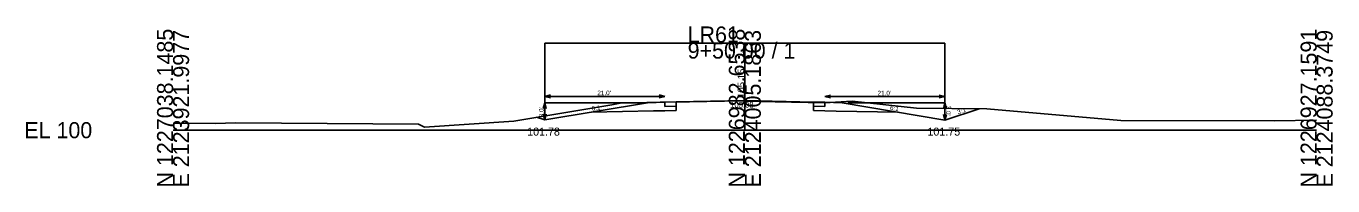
# Model space of a CAD drawing. Extents: x 2126751 to 2128979, y 1225108 to 1234639.
# Drawn here: x 2126750.9 to 2126979.4, y 1234607.5 to 1234635.3 of the extents above; entities that cross this region are included whole.
import ezdxf

# ---------------------------------------------------------------- set-up
doc = ezdxf.new("R2010")
doc.units = 0
for name, color, linetype in [('XS_CELL', 7, 'Continuous'), ('XS_M_DITCH', 7, 'Continuous'), ('XS_P_FINISHED_GRADE', 7, 'Continuous'), ('XS_P_FINISHED_GRADE_ELEV_TX', 7, 'Continuous'), ('XS_P_SUBGRADE_GRANULAR', 7, 'Continuous'), ('XS_P_SUBGRADE_LEVELING', 7, 'Continuous'), ('XS_P_SUBGRADE_PAVEMENT', 7, 'Continuous'), ('XS_P_TX_CLEARZONE', 7, 'Continuous'), ('XS_P_TX_DCH', 7, 'Continuous'), ('XS_P_TX_FS_BS', 7, 'Continuous'), ('XS_X_GROUND', 7, 'Continuous'), ('XS_X_GROUND_TX', 7, 'Continuous')]:
    doc.layers.add(name, color=color, linetype=linetype)

msp = doc.modelspace()

# ---------------------------------------------------------------- linework, layer by layer
at = {"layer": 'XS_CELL'}
for p, q in [((2126876.61, 1234617.21), (2126876.61, 1234632.49)), ((2126776.61, 1234617.21), (2126876.61, 1234617.21)), ((2126876.61, 1234617.21), (2126976.61, 1234617.21))]:
    msp.add_line(p, q, dxfattribs=at)
at = {"layer": 'XS_M_DITCH'}
for p, q in [((2126841.61, 1234618.99), (2126841.61, 1234632.39)), ((2126841.61, 1234632.39), (2126911.61, 1234632.39)), ((2126911.61, 1234632.39), (2126911.61, 1234618.96))]:
    msp.add_line(p, q, dxfattribs=at)
at = {"layer": 'XS_P_FINISHED_GRADE'}
for p, q in [((2126864.61, 1234622.15), (2126876.61, 1234622.36)), ((2126876.61, 1234622.36), (2126888.61, 1234622.12)), ((2126859.61, 1234621.99), (2126841.61, 1234618.99)), ((2126862.61, 1234622.11), (2126859.61, 1234621.99)), ((2126864.61, 1234622.15), (2126862.61, 1234622.11)), ((2126888.61, 1234622.12), (2126890.61, 1234622.08)), ((2126890.61, 1234622.08), (2126893.61, 1234621.96)), ((2126893.61, 1234621.96), (2126911.61, 1234618.96)), ((2126911.61, 1234618.96), (2126917.61, 1234620.96)), ((2126841.61, 1234618.99), (2126840.19, 1234619.46))]:
    msp.add_line(p, q, dxfattribs=at)
at = {"layer": 'XS_P_SUBGRADE_GRANULAR'}
for p, q in [((2126860.61, 1234620.57), (2126849.79, 1234620.35)), ((2126862.61, 1234620.61), (2126860.61, 1234620.57)), ((2126864.61, 1234620.65), (2126862.61, 1234620.61)), ((2126864.61, 1234620.65), (2126864.61, 1234621.4)), ((2126888.61, 1234620.62), (2126888.61, 1234621.37)), ((2126888.61, 1234620.62), (2126890.61, 1234620.58)), ((2126890.61, 1234620.58), (2126892.61, 1234620.54)), ((2126892.61, 1234620.54), (2126903.43, 1234620.33))]:
    msp.add_line(p, q, dxfattribs=at)
at = {"layer": 'XS_P_SUBGRADE_LEVELING'}
for p, q in [((2126866.95, 1234622.17), (2126876.07, 1234622.3)), ((2126876.07, 1234622.3), (2126876.61, 1234622.29)), ((2126876.61, 1234622.29), (2126881.92, 1234622.17)), ((2126864.61, 1234622.15), (2126866.95, 1234622.17)), ((2126881.92, 1234622.17), (2126888.61, 1234622.03)), ((2126888.61, 1234622.12), (2126888.61, 1234622.03))]:
    msp.add_line(p, q, dxfattribs=at)
at = {"layer": 'XS_P_SUBGRADE_PAVEMENT'}
for p, q in [((2126862.61, 1234621.36), (2126862.61, 1234622.11)), ((2126864.61, 1234621.4), (2126862.61, 1234621.36)), ((2126864.61, 1234621.4), (2126864.61, 1234622.15)), ((2126888.61, 1234621.37), (2126888.61, 1234622.03)), ((2126888.61, 1234621.37), (2126890.61, 1234621.33)), ((2126890.61, 1234621.33), (2126890.61, 1234622.08))]:
    msp.add_line(p, q, dxfattribs=at)
at = {"layer": 'XS_P_TX_CLEARZONE'}
for p, q in [((2126841.61, 1234623.11), (2126842.61, 1234623.36)), ((2126841.61, 1234623.11), (2126842.61, 1234622.86)), ((2126862.61, 1234623.11), (2126841.61, 1234623.11)), ((2126862.61, 1234623.11), (2126861.61, 1234623.36)), ((2126862.61, 1234623.11), (2126861.61, 1234622.86)), ((2126890.61, 1234623.08), (2126891.61, 1234623.33)), ((2126890.61, 1234623.08), (2126891.61, 1234622.83)), ((2126890.61, 1234623.08), (2126911.61, 1234623.08)), ((2126911.61, 1234623.08), (2126910.61, 1234623.33)), ((2126911.61, 1234623.08), (2126910.61, 1234622.83)), ((2126841.61, 1234621.99), (2126841.36, 1234620.99)), ((2126841.61, 1234618.99), (2126841.36, 1234619.99)), ((2126841.61, 1234621.99), (2126841.86, 1234620.99)), ((2126841.61, 1234621.99), (2126841.61, 1234618.99)), ((2126858.61, 1234621.99), (2126841.61, 1234621.99)), ((2126841.61, 1234618.99), (2126841.86, 1234619.99)), ((2126894.61, 1234621.96), (2126911.61, 1234621.96)), ((2126911.61, 1234621.96), (2126911.36, 1234620.96)), ((2126911.61, 1234618.96), (2126911.36, 1234619.96)), ((2126911.61, 1234621.96), (2126911.61, 1234618.96)), ((2126911.61, 1234621.96), (2126911.86, 1234620.96)), ((2126911.61, 1234618.96), (2126911.86, 1234619.96))]:
    msp.add_line(p, q, dxfattribs=at)
at = {"layer": 'XS_X_GROUND'}
for p, q in [((2126866.95, 1234622.17), (2126876.07, 1234622.3)), ((2126876.07, 1234622.3), (2126876.61, 1234622.29)), ((2126876.61, 1234622.29), (2126881.92, 1234622.17)), ((2126890.52, 1234621.99), (2126895.39, 1234622.28)), ((2126895.39, 1234622.28), (2126906.65, 1234621.02)), ((2126836.18, 1234618.8), (2126853.32, 1234621.61)), ((2126853.32, 1234621.61), (2126854.79, 1234621.91)), ((2126854.79, 1234621.91), (2126861.78, 1234622.11)), ((2126861.78, 1234622.11), (2126866.95, 1234622.17)), ((2126881.92, 1234622.17), (2126890.52, 1234621.99)), ((2126906.65, 1234621.02), (2126918.96, 1234620.96)), ((2126918.96, 1234620.96), (2126942.34, 1234618.89)), ((2126776.61, 1234618.42), (2126783.98, 1234618.36)), ((2126783.98, 1234618.36), (2126787.58, 1234618.49)), ((2126787.58, 1234618.49), (2126819.52, 1234618.23)), ((2126819.52, 1234618.23), (2126820.61, 1234617.71)), ((2126820.61, 1234617.71), (2126836.18, 1234618.8)), ((2126942.34, 1234618.89), (2126969.18, 1234618.82)), ((2126969.18, 1234618.82), (2126976.61, 1234618.97))]:
    msp.add_line(p, q, dxfattribs=at)

# ---------------------------------------------------------------- texts
at = {"layer": 'XS_CELL'}
for s, p in [('N 1227038.1485', (2126776.61, 1234607.21)), ('E 2123921.9977', (2126779.41, 1234607.21)), ('N 1226982.6538', (2126876.61, 1234607.21)), ('E 2124005.1863', (2126879.41, 1234607.21)), ('N 1226927.1591', (2126976.61, 1234607.21)), ('E 2124088.3749', (2126979.41, 1234607.21))]:
    msp.add_text(s, height=2.8, rotation=90, dxfattribs=at).set_placement(p)
for s, p in [('LR61', (2126866.61, 1234632.49)), ('9+50.00 / 1', (2126866.61, 1234629.69)), ('EL 100', (2126750.61, 1234615.81))]:
    msp.add_text(s, height=2.8, dxfattribs=at).set_placement(p)
at = {"layer": 'XS_P_FINISHED_GRADE_ELEV_TX'}
msp.add_text(' 105.15', height=1.25, rotation=90, dxfattribs=at).set_placement((2126876.61, 1234622.36))
at = {"layer": 'XS_P_TX_CLEARZONE'}
for p in [(2126850.82, 1234623.31), (2126899.82, 1234623.28)]:
    msp.add_text("21.0'", height=0.8, dxfattribs=at).set_placement(p)
for rotation, p in [(90, (2126841.41, 1234619.46)), (270, (2126911.81, 1234621.49))]:
    msp.add_text("3.0'", height=0.8, rotation=rotation, dxfattribs=at).set_placement(p)
at = {"layer": 'XS_P_TX_DCH'}
for s, p in [('101.78', (2126838.54, 1234616.26)), ('101.75', (2126908.54, 1234616.26))]:
    msp.add_text(s, height=1.4, dxfattribs=at).set_placement(p)
at = {"layer": 'XS_P_TX_FS_BS'}
for s, rotation, p in [('6:1', 9.4623, (2126849.89, 1234620.57)), ('6:1', 350.5377, (2126901.95, 1234620.77)), ('3:1', 18.4349, (2126913.9, 1234619.94))]:
    msp.add_text(s, height=0.8, rotation=rotation, dxfattribs=at).set_placement(p)
at = {"layer": 'XS_X_GROUND_TX'}
msp.add_text('105.08', height=1, dxfattribs=at).set_placement((2126874.05, 1234621.13))

doc.saveas('drawing.dxf')
